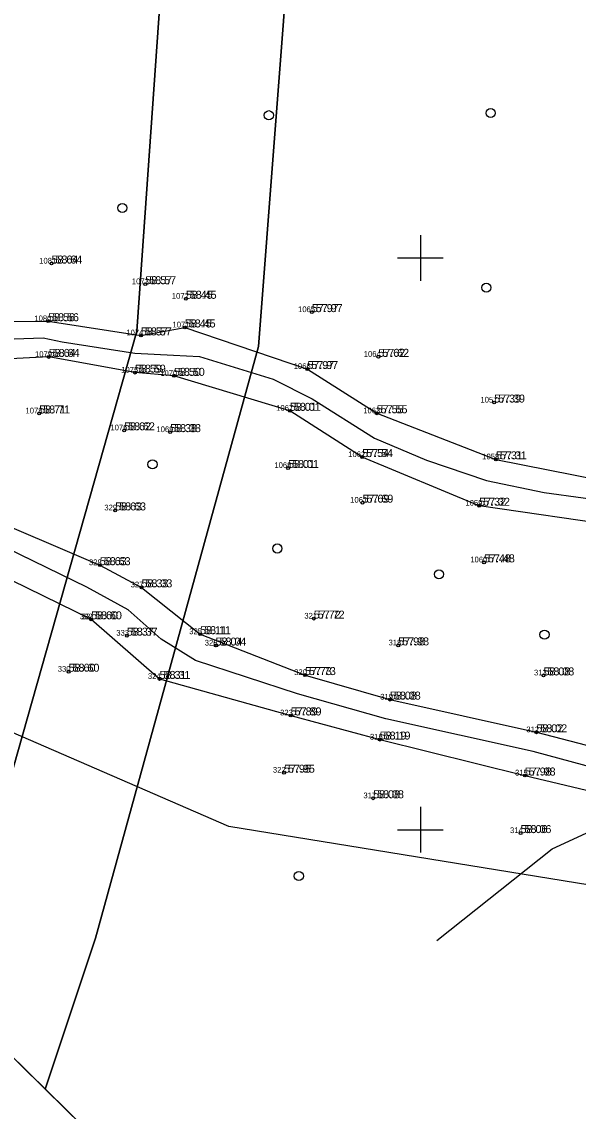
# Model space of a CAD drawing. Extents: x 554846 to 556995, y 6445875 to 6446723.
# Drawn here: x 555215.1 to 555263.8, y 6446025.4 to 6446120.7 of the extents above; entities that cross this region are included whole.
import ezdxf

# ---------------------------------------------------------------- set-up
doc = ezdxf.new("R2010")
doc.units = 0
for name, color, linetype in [('HALJASTUS', 7, 'Continuous'), ('KORGUS-EH2000', 7, 'Continuous'), ('MOOTKORG-EH2000', 7, 'Continuous'), ('MOOTMPUNKT', 7, 'Continuous'), ('MOOTNR', 7, 'Continuous'), ('MOOTPIIR', 7, 'Continuous'), ('PIIR', 7, 'Continuous'), ('SITRASS', 7, 'Continuous'), ('TEE', 7, 'Continuous'), ('VORK', 7, 'Continuous')]:
    doc.layers.add(name, color=color, linetype=linetype)

msp = doc.modelspace()

# ---------------------------------------------------------------- linework, layer by layer
at = {"layer": 'HALJASTUS'}
for centre in [(555236.743, 6446112.478), (555256.145, 6446112.667), (555223.934, 6446104.374), (555255.768, 6446097.4), (555226.571, 6446081.945), (555237.496, 6446074.594), (555251.624, 6446072.333), (555260.854, 6446067.055), (555239.368, 6446045.946)]:
    msp.add_circle(centre, 0.4, dxfattribs=at)
at = {"layer": 'KORGUS-EH2000'}
for centre in [(555217.742, 6446099.507), (555225.945, 6446097.704), (555229.488, 6446096.427), (555240.503, 6446095.26), (555217.445, 6446094.464), (555229.4, 6446093.92), (555225.561, 6446093.224), (555217.5, 6446091.342), (555246.321, 6446091.35), (555225.04, 6446089.968), (555228.452, 6446089.687), (555240.115, 6446090.283), (555238.588, 6446086.629), (555256.449, 6446087.352), (555216.669, 6446086.398), (555246.177, 6446086.414), (555224.09, 6446084.922), (555228.116, 6446084.767), (555244.915, 6446082.585), (555256.606, 6446082.386), (555238.429, 6446081.627), (555244.937, 6446078.596), (555255.136, 6446078.331), (555223.312, 6446077.92), (555255.562, 6446073.375), (555221.965, 6446073.13), (555225.614, 6446071.192), (555221.204, 6446068.398), (555221.209, 6446068.395), (555240.676, 6446068.459), (555224.332, 6446066.967), (555230.738, 6446067.097), (555232.089, 6446066.102), (555248.062, 6446066.116), (555219.238, 6446063.813), (555227.196, 6446063.185), (555239.91, 6446063.522), (555260.759, 6446063.491), (555247.335, 6446061.378), (555238.66, 6446059.992), (555260.141, 6446058.516), (555246.439, 6446057.88), (555238.075, 6446054.986), (555259.125, 6446054.737), (555245.867, 6446052.748), (555258.761, 6446049.702)]:
    msp.add_circle(centre, 0.125, dxfattribs=at)
at = {"layer": 'MOOTMPUNKT'}
for centre in [(555217.742, 6446099.507), (555225.945, 6446097.704), (555229.488, 6446096.427), (555240.503, 6446095.26), (555217.445, 6446094.464), (555229.4, 6446093.92), (555225.561, 6446093.224), (555217.5, 6446091.342), (555246.321, 6446091.35), (555225.04, 6446089.968), (555228.452, 6446089.687), (555240.115, 6446090.283), (555238.588, 6446086.629), (555256.449, 6446087.352), (555216.669, 6446086.398), (555246.177, 6446086.414), (555224.09, 6446084.922), (555228.116, 6446084.767), (555244.915, 6446082.585), (555256.606, 6446082.386), (555238.429, 6446081.627), (555244.937, 6446078.596), (555255.136, 6446078.331), (555223.312, 6446077.92), (555255.562, 6446073.375), (555221.965, 6446073.13), (555225.614, 6446071.192), (555221.204, 6446068.398), (555221.209, 6446068.395), (555240.676, 6446068.459), (555224.332, 6446066.967), (555230.738, 6446067.097), (555232.149, 6446066.108), (555248.062, 6446066.116), (555219.238, 6446063.813), (555227.196, 6446063.185), (555239.91, 6446063.522), (555260.759, 6446063.491), (555247.335, 6446061.378), (555238.66, 6446059.992), (555260.141, 6446058.516), (555246.439, 6446057.88), (555238.075, 6446054.986), (555259.125, 6446054.737), (555245.867, 6446052.748), (555258.761, 6446049.702)]:
    msp.add_circle(centre, 0.125, dxfattribs=at)
at = {"layer": 'MOOTPIIR'}
msp.add_lwpolyline([(555318.618, 6446036.416), (555233.239, 6446050.269), (555125.444, 6446097.106), (555048.306, 6446167.69), (555006.11, 6446211.888), (555013.692, 6446244.542), (555031.164, 6446248.5), (555054.569, 6446254.767), (555085.226, 6446285.771), (555124.125, 6446294.677), (555188.077, 6446295.667), (555274.445, 6446293.028)], dxfattribs=at)
at = {"layer": 'PIIR'}
msp.add_lwpolyline([(555289.66, 6445948.39), (555259.76, 6445985.47), (555217.2, 6446027.3), (555221.59, 6446040.5), (555235.83, 6446092.25), (555238.76, 6446130.23), (555175.25, 6446281.89), (555176.83, 6446322.12), (555182.27, 6446354.13), (555578.67, 6446397.08)], dxfattribs=at)
for points in [[(555217.2, 6446027.3), (555207.97, 6446036.37), (555211.87, 6446046.6), (555225.2, 6446093.61), (555227.69, 6446128.87), (555162.59, 6446280.08), (555164.63, 6446323.25), (555170.51, 6446352.86), (555182.27, 6446354.13), (555176.83, 6446322.12), (555175.25, 6446281.89), (555238.76, 6446130.23), (555235.83, 6446092.25), (555221.59, 6446040.5)], [(554929.82, 6446275.15), (554900.05, 6446303.23), (554899.45, 6446307.62), (554900.2, 6446312.5), (554902.6, 6446318.8), (554905.25, 6446321.45), (555070.62, 6446339.03), (555070.32, 6446342.01), (555170.51, 6446352.86), (555164.63, 6446323.25), (555162.59, 6446280.08), (555227.69, 6446128.87), (555225.2, 6446093.61), (555211.87, 6446046.6), (555207.97, 6446036.37), (555171.51, 6446072.2), (555063.52, 6446162.84), (555018.2, 6446200.67), (554979.69, 6446232.72)], [(554905.25, 6446321.45), (554902.6, 6446318.8), (554900.2, 6446312.5), (554899.45, 6446307.62), (554900.05, 6446303.23), (554929.82, 6446275.15), (554979.69, 6446232.72), (555018.2, 6446200.67), (555063.52, 6446162.84), (555171.51, 6446072.2), (555259.76, 6445985.47), (555245.85, 6445971.1), (555158.25, 6446057.2), (555050.97, 6446147.25), (555006.25, 6446184.5), (554967.02, 6446217.23), (554918.28, 6446258.46), (554879.79, 6446294.54), (554861.5, 6446307.3), (554853.6, 6446312.1), (554845.9, 6446314.9)]]:
    msp.add_lwpolyline(points, close=True, dxfattribs=at)
at = {"layer": 'SITRASS'}
msp.add_lwpolyline([(555251.45, 6446040.324), (555261.531, 6446048.322), (555265.261, 6446050.033)], dxfattribs=at)
at = {"layer": 'TEE'}
for points in [[(555171.016, 6446125.765), (555174.131, 6446115.486), (555175.904, 6446111.504), (555178.798, 6446106.907), (555180.848, 6446105.365), (555188.922, 6446099.286), (555196.359, 6446094.27), (555199.419, 6446093.256), (555202.6, 6446092.74), (555209.409, 6446092.747), (555217.017, 6446093.016), (555218.682, 6446092.674), (555225.024, 6446091.676), (555228.414, 6446091.49), (555230.683, 6446091.366), (555237.134, 6446089.409), (555240.534, 6446087.672), (555245.997, 6446084.233), (555250.52, 6446082.314), (555255.765, 6446080.541), (555260.831, 6446079.486), (555267.633, 6446078.545)], [(555172.576, 6446126.307), (555176.276, 6446115.804), (555179.97, 6446108.114), (555187.169, 6446103.188), (555194.365, 6446098.26), (555198.585, 6446095.738), (555202.891, 6446094.409), (555209.552, 6446094.41), (555217.445, 6446094.464), (555225.561, 6446093.224), (555229.4, 6446093.92), (555240.115, 6446090.283), (555246.177, 6446086.414), (555256.606, 6446082.386), (555267.961, 6446080.125)], [(555267.574, 6446076.502), (555255.136, 6446078.331), (555244.915, 6446082.585), (555238.588, 6446086.629), (555228.452, 6446089.687), (555225.04, 6446089.968), (555217.5, 6446091.342), (555209.073, 6446090.903), (555203.074, 6446090.514), (555195.92, 6446091.645), (555192.83, 6446092.916), (555184.355, 6446100.114), (555177.346, 6446105.248), (555172.224, 6446113.573), (555169.119, 6446125.329)], [(555124.201, 6446120.525), (555134.694, 6446110.192), (555138.923, 6446106.992), (555147.112, 6446103.24), (555157.994, 6446097.552), (555169.673, 6446089.148), (555174.368, 6446087.465), (555180.317, 6446085.359), (555188.834, 6446083.739), (555197.254, 6446082.751), (555204.21, 6446081.262), (555210.99, 6446077.82), (555221.965, 6446073.13), (555225.614, 6446071.192), (555230.738, 6446067.097), (555239.91, 6446063.522), (555247.335, 6446061.378), (555260.141, 6446058.516), (555267.449, 6446056.625)], [(555276.361, 6446052.392), (555259.849, 6446056.848), (555246.973, 6446059.704), (555239.262, 6446061.875), (555230.339, 6446064.792), (555227.32, 6446066.675), (555224.447, 6446069.239), (555220.829, 6446071.204), (555210.28, 6446076.33), (555204.512, 6446079.474), (555202.383, 6446079.991), (555199.511, 6446080.689), (555194.887, 6446081.333), (555188.127, 6446081.995), (555180.959, 6446083.261), (555177.848, 6446084.274), (555173.596, 6446085.66), (555168.514, 6446088.256), (555157.242, 6446096.118), (555146.605, 6446101.873), (555138.031, 6446105.457), (555133.219, 6446108.823), (555123.24, 6446119.403)], [(555121.821, 6446118.425), (555132.201, 6446106.885), (555136.885, 6446103.671), (555145.513, 6446100.35), (555155.937, 6446094.865), (555167.81, 6446086.546), (555172.972, 6446084.239), (555180.055, 6446081.191), (555187.706, 6446079.742), (555196.668, 6446078.85), (555202.713, 6446078.031), (555208.62, 6446074.566), (555221.204, 6446068.398), (555227.196, 6446063.185), (555238.66, 6446059.992), (555246.439, 6446057.88), (555259.125, 6446054.737), (555266.253, 6446053.038)]]:
    msp.add_lwpolyline(points, dxfattribs=at)
at = {"layer": 'VORK'}
for p, q in [((555250, 6446102), (555250, 6446098)), ((555248, 6446100), (555252, 6446100)), ((555250, 6446052), (555250, 6446048)), ((555248, 6446050), (555252, 6446050))]:
    msp.add_line(p, q, dxfattribs=at)

# ---------------------------------------------------------------- texts
at = {"layer": 'KORGUS-EH2000'}
for s, p in [('58.64', (555218.092, 6446099.507)), ('58.57', (555226.295, 6446097.704)), ('58.45', (555229.838, 6446096.427)), ('57.97', (555240.853, 6446095.26)), ('58.56', (555217.795, 6446094.464)), ('58.45', (555229.75, 6446093.92)), ('58.57', (555225.911, 6446093.224)), ('58.64', (555217.85, 6446091.342)), ('57.62', (555246.671, 6446091.35)), ('58.59', (555225.39, 6446089.968)), ('57.97', (555240.465, 6446090.283)), ('58.50', (555228.802, 6446089.687)), ('57.39', (555256.799, 6446087.352)), ('58.71', (555217.019, 6446086.398)), ('58.01', (555238.938, 6446086.629)), ('57.55', (555246.527, 6446086.414)), ('58.62', (555224.44, 6446084.922)), ('58.38', (555228.466, 6446084.767)), ('57.54', (555245.265, 6446082.585)), ('57.31', (555256.956, 6446082.386)), ('58.01', (555238.779, 6446081.627)), ('57.69', (555245.287, 6446078.596)), ('58.63', (555223.662, 6446077.92)), ('57.32', (555255.486, 6446078.331)), ('58.63', (555222.315, 6446073.13)), ('57.48', (555255.912, 6446073.375)), ('58.33', (555225.964, 6446071.192)), ('58.60', (555221.554, 6446068.398)), ('58.60', (555221.559, 6446068.395)), ('57.72', (555241.026, 6446068.459)), ('58.37', (555224.682, 6446066.967)), ('58.11', (555231.088, 6446067.097)), ('58.04', (555232.439, 6446066.102)), ('57.98', (555248.412, 6446066.116)), ('58.60', (555219.588, 6446063.813)), ('58.31', (555227.546, 6446063.185)), ('57.73', (555240.26, 6446063.522)), ('58.08', (555261.109, 6446063.491)), ('58.08', (555247.685, 6446061.378)), ('57.89', (555239.01, 6446059.992)), ('58.02', (555260.491, 6446058.516)), ('58.19', (555246.789, 6446057.88)), ('57.95', (555238.425, 6446054.986)), ('57.98', (555259.475, 6446054.737)), ('58.08', (555246.217, 6446052.748)), ('58.06', (555259.111, 6446049.702))]:
    msp.add_text(s, height=0.7, dxfattribs=at).set_placement(p)
at = {"layer": 'MOOTKORG-EH2000'}
for s, p in [('58.64', (555217.742, 6446099.507)), ('58.57', (555225.945, 6446097.704)), ('58.45', (555229.488, 6446096.427)), ('57.97', (555240.503, 6446095.26)), ('58.56', (555217.445, 6446094.464)), ('58.45', (555229.4, 6446093.92)), ('58.57', (555225.561, 6446093.224)), ('58.64', (555217.5, 6446091.342)), ('57.62', (555246.321, 6446091.35)), ('58.59', (555225.04, 6446089.968)), ('57.97', (555240.115, 6446090.283)), ('58.50', (555228.452, 6446089.687)), ('57.39', (555256.449, 6446087.352)), ('58.71', (555216.669, 6446086.398)), ('58.01', (555238.588, 6446086.629)), ('57.55', (555246.177, 6446086.414)), ('58.62', (555224.09, 6446084.922)), ('58.38', (555228.116, 6446084.767)), ('57.54', (555244.915, 6446082.585)), ('57.31', (555256.606, 6446082.386)), ('58.01', (555238.429, 6446081.627)), ('57.69', (555244.937, 6446078.596)), ('58.63', (555223.312, 6446077.92)), ('57.32', (555255.136, 6446078.331)), ('58.63', (555221.965, 6446073.13)), ('57.48', (555255.562, 6446073.375)), ('58.33', (555225.614, 6446071.192)), ('58.60', (555221.204, 6446068.398)), ('58.60', (555221.209, 6446068.395)), ('57.72', (555240.676, 6446068.459)), ('58.37', (555224.332, 6446066.967)), ('58.11', (555230.738, 6446067.097)), ('58.04', (555232.089, 6446066.102)), ('57.98', (555248.062, 6446066.116)), ('58.60', (555219.238, 6446063.813)), ('58.31', (555227.196, 6446063.185)), ('57.73', (555239.91, 6446063.522)), ('58.08', (555260.759, 6446063.491)), ('58.08', (555247.335, 6446061.378)), ('57.89', (555238.66, 6446059.992)), ('58.02', (555260.141, 6446058.516)), ('58.19', (555246.439, 6446057.88)), ('57.95', (555238.075, 6446054.986)), ('57.98', (555259.125, 6446054.737)), ('58.08', (555245.867, 6446052.748)), ('58.06', (555258.761, 6446049.702))]:
    msp.add_text(s, height=0.7, dxfattribs=at).set_placement(p)
at = {"layer": 'MOOTNR'}
for s, p in [('1081', (555216.667, 6446099.507)), ('1073', (555224.77, 6446097.704)), ('1072', (555228.263, 6446096.427)), ('1065', (555239.303, 6446095.26)), ('1080', (555216.245, 6446094.464)), ('1071', (555228.325, 6446093.92)), ('1074', (555224.286, 6446093.224)), ('1079', (555216.3, 6446091.342)), ('1064', (555245.046, 6446091.35)), ('1066', (555238.915, 6446090.283)), ('1075', (555223.84, 6446089.968)), ('1070', (555227.252, 6446089.687)), ('1057', (555255.249, 6446087.352)), ('1078', (555215.469, 6446086.398)), ('1067', (555237.388, 6446086.629)), ('1063', (555245.002, 6446086.414)), ('1076', (555222.89, 6446084.922)), ('1069', (555226.916, 6446084.767)), ('1062', (555243.69, 6446082.585)), ('1058', (555255.406, 6446082.386)), ('1068', (555237.229, 6446081.627)), ('1061', (555243.862, 6446078.596)), ('329', (555222.362, 6446077.92)), ('1059', (555253.936, 6446078.331)), ('328', (555221.015, 6446073.13)), ('1060', (555254.362, 6446073.375)), ('327', (555224.664, 6446071.192)), ('332', (555220.229, 6446068.398)), ('331', (555220.384, 6446068.395)), ('321', (555239.851, 6446068.459)), ('333', (555223.407, 6446066.967)), ('325', (555229.788, 6446067.097)), ('326', (555231.139, 6446066.102)), ('8', (555231.899, 6446066.108)), ('318', (555247.212, 6446066.116)), ('330', (555218.288, 6446063.813)), ('320', (555238.96, 6446063.522)), ('313', (555259.934, 6446063.491)), ('324', (555226.171, 6446063.185)), ('319', (555246.485, 6446061.378)), ('323', (555237.735, 6446059.992)), ('316', (555245.589, 6446057.88)), ('312', (555259.266, 6446058.516)), ('322', (555237.1, 6446054.986)), ('315', (555258.275, 6446054.737)), ('317', (555245.017, 6446052.748)), ('314', (555257.836, 6446049.702))]:
    msp.add_text(s, height=0.5, dxfattribs=at).set_placement(p)

doc.saveas('drawing.dxf')
